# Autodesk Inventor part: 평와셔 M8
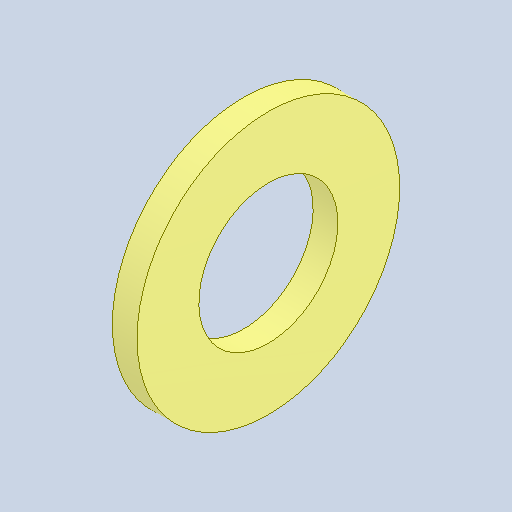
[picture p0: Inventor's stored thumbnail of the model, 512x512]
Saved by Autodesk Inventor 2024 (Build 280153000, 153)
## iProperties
Created: 2024-11
Part Number: 평와셔 M8
Material: 강철, 연강
Description: 평면 와셔
Document SubType Name: Modeling
Designer: user
Density: 7.85 g/cm^3
Appearance: 기본값
Author: jhkim
Sending System: Autodesk Inventor 2025
Preprocessor: ST-DEVELOPER v20
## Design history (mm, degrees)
node "평와셔 M81"
node "솔리드1"
body "Solid1"
